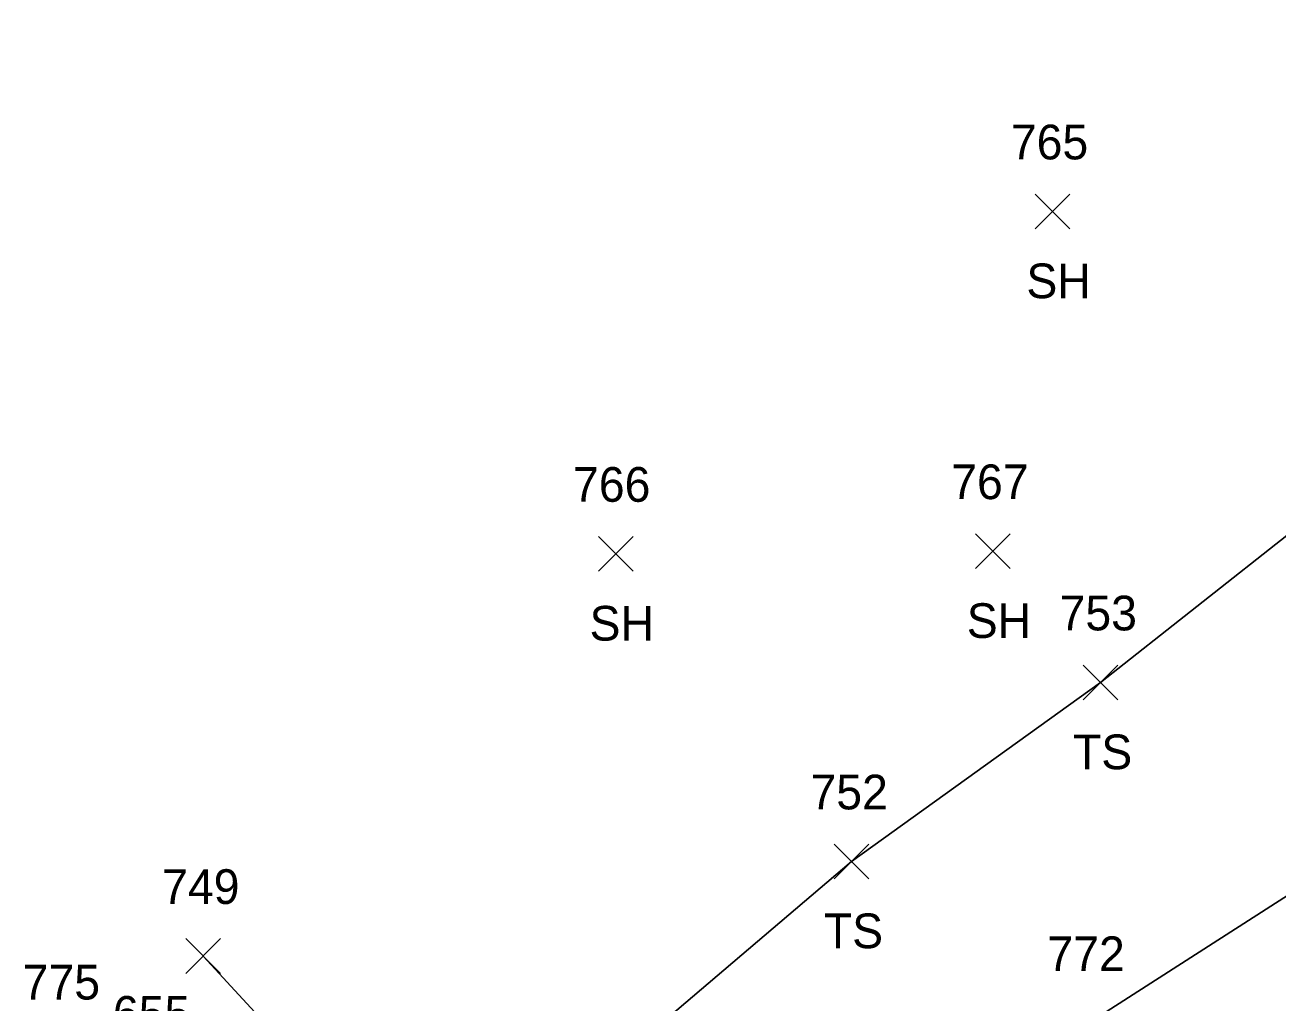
# Model space of a CAD drawing. Extents: x 1528286 to 1556263, y 492387 to 508952.
# Drawn here: x 1528469 to 1528541.2, y 492737.7 to 492794 of the extents above; entities that cross this region are included whole.
import ezdxf

# ---------------------------------------------------------------- set-up
doc = ezdxf.new("R2010")
doc.units = 0
for name, color, linetype in [('L_A', 7, 'Continuous'), ('L_I', 7, 'Continuous'), ('L_TIC', 7, 'Continuous'), ('LAWA', 7, 'Continuous'), ('LELB', 7, 'Continuous')]:
    doc.layers.add(name, color=color, linetype=linetype)

msp = doc.modelspace()

# ---------------------------------------------------------------- linework, layer by layer
at = {"layer": 'L_TIC'}
for points in [[(1528527.253, 492782.301), (1528529.253, 492784.301)], [(1528529.253, 492782.301), (1528527.253, 492784.301)], [(1528527.253, 492782.301), (1528529.253, 492784.301)], [(1528529.253, 492782.301), (1528527.253, 492784.301)], [(1528502.059, 492762.569), (1528504.059, 492764.569)], [(1528504.059, 492762.569), (1528502.059, 492764.569)], [(1528502.059, 492762.569), (1528504.059, 492764.569)], [(1528504.059, 492762.569), (1528502.059, 492764.569)], [(1528523.812, 492762.721), (1528525.812, 492764.721)], [(1528525.812, 492762.721), (1528523.812, 492764.721)], [(1528523.812, 492762.721), (1528525.812, 492764.721)], [(1528525.812, 492762.721), (1528523.812, 492764.721)], [(1528530.015, 492755.158), (1528532.015, 492757.158)], [(1528532.015, 492755.158), (1528530.015, 492757.158)], [(1528530.015, 492755.158), (1528532.015, 492757.158)], [(1528532.015, 492755.158), (1528530.015, 492757.158)], [(1528515.649, 492744.843), (1528517.649, 492746.843)], [(1528517.649, 492744.843), (1528515.649, 492746.843)], [(1528515.649, 492744.843), (1528517.649, 492746.843)], [(1528517.649, 492744.843), (1528515.649, 492746.843)], [(1528478.267, 492739.393), (1528480.267, 492741.393)], [(1528480.267, 492739.393), (1528478.267, 492741.393)], [(1528478.267, 492739.393), (1528480.267, 492741.393)], [(1528480.267, 492739.393), (1528478.267, 492741.393)]]:
    msp.add_lwpolyline(points, dxfattribs=at)
at = {"layer": 'LAWA'}
msp.add_lwpolyline([(1528662.937, 492830.692), (1528634.182, 492809.012), (1528604.188, 492788.279), (1528566.961, 492760.007), (1528530.313, 492736.522), (1528502.638, 492712.533), (1528486.776, 492718.401), (1528471.218, 492734.886)], dxfattribs=at)
msp.add_lwpolyline([(1528662.937, 492830.692), (1528634.182, 492809.012), (1528604.188, 492788.279), (1528566.961, 492760.007), (1528530.313, 492736.522), (1528502.638, 492712.533), (1528486.776, 492718.401), (1528471.218, 492734.886)], dxfattribs=at)
at = {"layer": 'LELB'}
msp.add_lwpolyline([(1528479.267, 492740.393), (1528490.259, 492728.467), (1528495.219, 492727.605), (1528516.649, 492745.843), (1528531.015, 492756.158), (1528553.244, 492773.675), (1528563.708, 492774.042), (1528594.12, 492792.873), (1528616.34, 492816.289), (1528631.227, 492827.673), (1528655.587, 492852.622)], dxfattribs=at)
msp.add_lwpolyline([(1528479.267, 492740.393), (1528490.259, 492728.467), (1528495.219, 492727.605), (1528516.649, 492745.843), (1528531.015, 492756.158), (1528553.244, 492773.675), (1528563.708, 492774.042), (1528594.12, 492792.873), (1528616.34, 492816.289), (1528631.227, 492827.673), (1528655.587, 492852.622)], dxfattribs=at)

# ---------------------------------------------------------------- texts
at = {"layer": 'L_A'}
for s, p in [('SH', (1528526.741, 492778.301)), ('SH', (1528526.741, 492778.301)), ('SH', (1528501.547, 492758.569)), ('SH', (1528501.547, 492758.569)), ('SH', (1528523.3, 492758.721)), ('SH', (1528523.3, 492758.721)), ('TS', (1528529.425, 492751.158)), ('TS', (1528529.425, 492751.158)), ('TS', (1528515.058, 492740.843)), ('TS', (1528515.058, 492740.843))]:
    msp.add_text(s, height=2, dxfattribs=at).set_placement(p)
at = {"layer": 'L_I'}
for s, p in [('765', (1528525.843, 492786.301)), ('765', (1528525.843, 492786.301)), ('766', (1528500.594, 492766.569)), ('766', (1528500.594, 492766.569)), ('767', (1528522.403, 492766.721)), ('767', (1528522.403, 492766.721)), ('753', (1528528.653, 492759.158)), ('753', (1528528.653, 492759.158)), ('752', (1528514.287, 492748.843)), ('752', (1528514.287, 492748.843)), ('749', (1528476.897, 492743.393)), ('749', (1528476.897, 492743.393)), ('772', (1528527.95, 492739.522)), ('772', (1528527.95, 492739.522)), ('775', (1528468.856, 492737.886)), ('775', (1528468.856, 492737.886)), ('655', (1528474.06, 492736.086)), ('655', (1528474.06, 492736.086))]:
    msp.add_text(s, height=2, dxfattribs=at).set_placement(p)

doc.saveas('drawing.dxf')
